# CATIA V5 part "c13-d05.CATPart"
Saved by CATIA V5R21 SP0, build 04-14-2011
Part number: Part1
Bounding box of the stored display mesh (mm): x -62.5 to 62.5, y -75 to 75, z 0 to 20
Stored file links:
  D:\CATIA V5R21 E-RESOURCES\CATIA-V5R21\catia-v5r21-Prts\c13_catia_v5r21_prt\c13_catia_v5r21_figr_13-26\c13-d05.CATPart
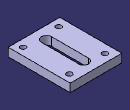
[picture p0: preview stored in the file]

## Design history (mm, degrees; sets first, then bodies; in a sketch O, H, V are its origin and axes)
Body1 (main body)
  Sketch1 on xy-plane, origin (0, 0, 0), H (1, 0, 0), V (0, 1, 0)
    line L1 (62.5, 75) -> (62.5, -75)
    line L2 (62.5, -75) -> (-62.5, -75)
    line L3 (-62.5, -75) -> (-62.5, 75)
    line L4 (-62.5, 75) -> (62.5, 75)
    length L1 = 150
    length L2 = 125
    vertical: L1 V, L3 V
    horizontal: L2 H, L4 H
    equidistance: L1 L3 O, L2 L4 O
  Pad1: profile Sketch1, direction (0, 0, 1), length 20
  Sketch2 on face of Pad1, origin (0, 0, 20), H (1, 0, 0), V (0, 1, 0)
    construction line L1 (0, 45) -> (0, -45)
    point P1 (0, 45)
    line L2 (12, 45) -> (12, -45)
    line L3 (-12, -45) -> (-12, 45)
    arc A1 centre (0, -45) radius 12 from (12, -45) to (-12, -45) cw
    arc A2 centre (0, 45) radius 12 from (-12, 45) to (12, 45) cw
    length L1 = 90
    radius A2 = 12
    coincidence: P1 V
    vertical: L1 V
    tangency: A1 L2, A2 L2, A1 L3, A2 L3
    parallelism: L1 L2
    midpoint: O L1
  Pocket1: profile Sketch2, direction (0, 0, -1), through (limit type 3)
  Sketch3 on face of Pad1, origin (38.7626, -18.4621, 20), H (1, 0, 0), V (0, 1, 0)
    point P1 (5.7374, -38.5379)
    reference projected line E1 (-101.2626, -56.5379) -> (23.7374, -56.5379) from edge [face of Pad1 | face of Pad1]
    reference projected line E2 (23.7374, -56.5379) -> (23.7374, 93.4621) from edge [face of Pad1 | face of Pad1]
    distance P1 E1 = 18
    distance P1 E2 = 18
  Hole1: placed by Sketch3, at (44.5, -57, 20) direction (0, 0, -1), diameter 13, through (limit type 3)
  RectPattern1: of Hole1, direction 1 instances 2, spacing 86, along edge [face of Pad1 | face of Pad1] reversed, direction 2 instances 2, spacing 112, along edge [face of Pad1 | face of Pad1]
